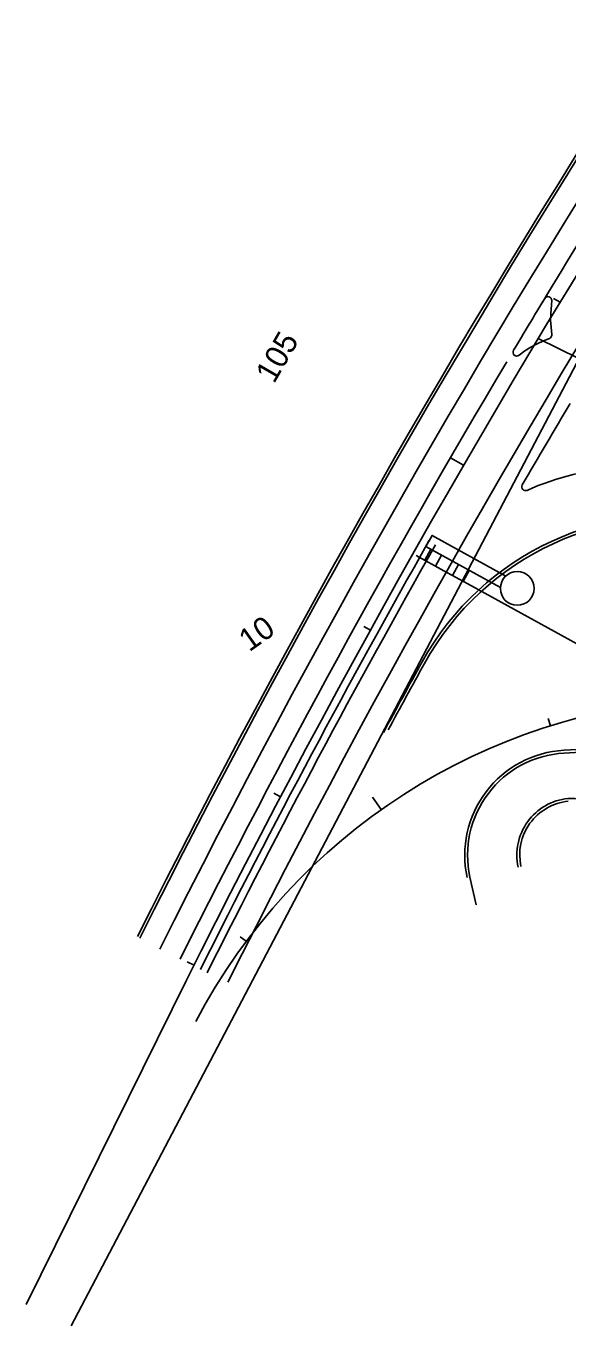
# Model space of a CAD drawing. Extents: x 2338610 to 2351914, y 366540 to 376484.
# Drawn here: x 2345391 to 2345677, y 366762 to 367449 of the extents above; entities that cross this region are included whole.
import ezdxf

# ---------------------------------------------------------------- set-up
doc = ezdxf.new("R2010")
doc.units = 0
for name, color, linetype in [('RD_HC_Cl', 7, 'Continuous'), ('RD_HC_CL_Rel', 7, 'Continuous'), ('RD_PD_Final_LnLine', 7, 'Continuous'), ('RD_PD_Final_TrvlWay', 7, 'Continuous'), ('RD_PD_FOC', 7, 'Continuous'), ('TR SN EXTRUDED PANEL SIGNS- MOUNTED OVERHEAD', 7, 'Continuous'), ('TR SN UNASSIGNED 7', 7, 'Continuous')]:
    doc.layers.add(name, color=color, linetype=linetype)

msp = doc.modelspace()

# ---------------------------------------------------------------- linework, layer by layer
at = {"layer": 'RD_HC_Cl'}
for p, q in [((2345775.2, 367448.54), (2345415.04, 366761.94)), ((2345775.2, 367448.54), (2345415.04, 366761.94)), ((2345775.2, 367448.54), (2345415.04, 366761.94)), ((2345775.2, 367448.54), (2345415.04, 366761.94)), ((2345391.17, 366773.23), (2345468.3, 366929.27))]:
    msp.add_line(p, q, dxfattribs=at)
for centre, radius, start, end in [((2349947.04, 364715.46), 4996, 141.09378, 153.6971), ((2345763.18, 366774.42), 319.03, 93.21556, 152.29466)]:
    msp.add_arc(centre, radius, start, end, dxfattribs=at)
at = {"layer": 'RD_HC_CL_Rel'}
msp.add_arc((2346316.34, 368577.71), 1450.39, 243.16427, 273.21556, dxfattribs=at)
at = {"layer": 'RD_PD_Final_LnLine'}
for p, q in [((2346049.1, 367086.04), (2345675.14, 367064.51)), ((2345625.49, 366999.07), (2345628.71, 366984.32))]:
    msp.add_line(p, q, dxfattribs=at)
for points in [[(2345668.69, 367303.49), (2345668.15, 367296.76), (2345668.1, 367293.09), (2345668.29, 367289.41), (2345668.73, 367285.65)], [(2345667.47, 367283.56), (2345664.26, 367282.3), (2345660.91, 367280.73), (2345657.67, 367278.94), (2345654.55, 367276.94), (2345651.44, 367274.63)]]:
    msp.add_lwpolyline(points, dxfattribs=at)
for centre, radius, start, end in [((2349947.04, 364715.46), 5028, 141.09378, 153.39961), ((2349947.04, 364715.46), 5016, 141.09378, 153.40546), ((2349947.04, 364715.46), 4976, 141.09378, 153.40022), ((2349947.04, 364715.46), 5004, 144.14093, 148.87068), ((2349947.04, 364715.46), 5004, 149.28654, 153.40546), ((2345731.57, 367040.21), 150, 78.32216, 151.12416), ((2349947.04, 364715.46), 4964, 151.12416, 151.61381), ((2345678.24, 367010.6), 54, 93.295, 192.32864), ((2345680.26, 367010.71), 30, 95.76247, 192.32864), ((2345678.06, 367000.57), 40, 12.6698, 91.15815)]:
    msp.add_arc(centre, radius, start, end, dxfattribs=at)
at = {"layer": 'RD_PD_Final_TrvlWay'}
for centre, radius, start, end in [((2349947.04, 364715.46), 5004, 148.84, 149.2061), ((2345666.7, 367303.64), 2, 355.43913, 148.84), ((2345666.74, 367285.42), 2, 291.35595, 6.67067), ((2345650.25, 367276.24), 2, 149.2061, 306.5069), ((2349947.04, 364715.46), 4964, 149.30759, 149.88443), ((2345716.48, 367066.19), 150, 74.80964, 113.92694), ((2345654.83, 367205.12), 2, 149.88443, 293.92694), ((2349947.04, 364715.46), 4992, 150.46159, 153.40546), ((2349947.04, 364715.46), 4988, 150.46159, 153.40546)]:
    msp.add_arc(centre, radius, start, end, dxfattribs=at)
at = {"layer": 'RD_PD_FOC'}
msp.add_line((2346049.02, 367087.54), (2345675.05, 367066.01), dxfattribs=at)
for centre, radius, start, end in [((2349947.04, 364715.46), 5029.5, 141.09378, 153.39864), ((2345731.57, 367040.21), 148.5, 78.32216, 151.12416), ((2349947.04, 364715.46), 4962.5, 151.12416, 151.58642), ((2345678.24, 367010.6), 55.5, 93.295, 192.32864), ((2345680.26, 367010.71), 28.5, 95.76247, 192.32864)]:
    msp.add_arc(centre, radius, start, end, dxfattribs=at)
at = {"layer": 'TR SN EXTRUDED PANEL SIGNS- MOUNTED OVERHEAD'}
for p, q in [((2345604.84, 367172.18), (2345601.62, 367166.33)), ((2345611.69, 367160.85), (2345597.07, 367168.91)), ((2345610.47, 367169.08), (2345607.26, 367163.26)), ((2345619.46, 367164.12), (2345616.24, 367158.28)), ((2345626.31, 367152.8), (2345611.69, 367160.85)), ((2345625.09, 367161.02), (2345621.88, 367155.2)), ((2345870.09, 367018.52), (2345626.31, 367152.8))]:
    msp.add_line(p, q, dxfattribs=at)
msp.add_lwpolyline([(2345644.41, 367158.03), (2345605.51, 367179.46), (2345602.28, 367173.59), (2345641.57, 367151.94)], dxfattribs=at)
msp.add_circle((2345650.46, 367151.5), 8.91, dxfattribs=at)
at = {"layer": 'TR SN UNASSIGNED 7'}
for p, q in [((2345673.08, 367302.61), (2345669.66, 367304.68)), ((2345622.16, 367216.55), (2345615.23, 367220.55)), ((2345572.97, 367129.49), (2345569.46, 367131.42)), ((2345667.95, 367078.91), (2345666.76, 367082.72)), ((2345525.53, 367041.46), (2345521.99, 367043.32)), ((2345578.71, 367034.71), (2345574.08, 367041.23)), ((2345507.44, 366965.14), (2345504.23, 366967.53)), ((2345479.86, 366952.5), (2345476.28, 366954.29))]:
    msp.add_line(p, q, dxfattribs=at)

# ---------------------------------------------------------------- texts
for s, rotation, p in [('105', 59.95911, (2345522.09, 367259.25)), ('10', 35.32679, (2345509.03, 367117.7))]:
    msp.add_text(s, height=12, rotation=rotation, dxfattribs=at).set_placement(p)

doc.saveas('drawing.dxf')
